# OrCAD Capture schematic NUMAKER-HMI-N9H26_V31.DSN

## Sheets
1 Audio: size A; title: NuMaker-HMI-N9H26; rev: 3.0; company: nuvoTon Technology Corp.; note: Audio
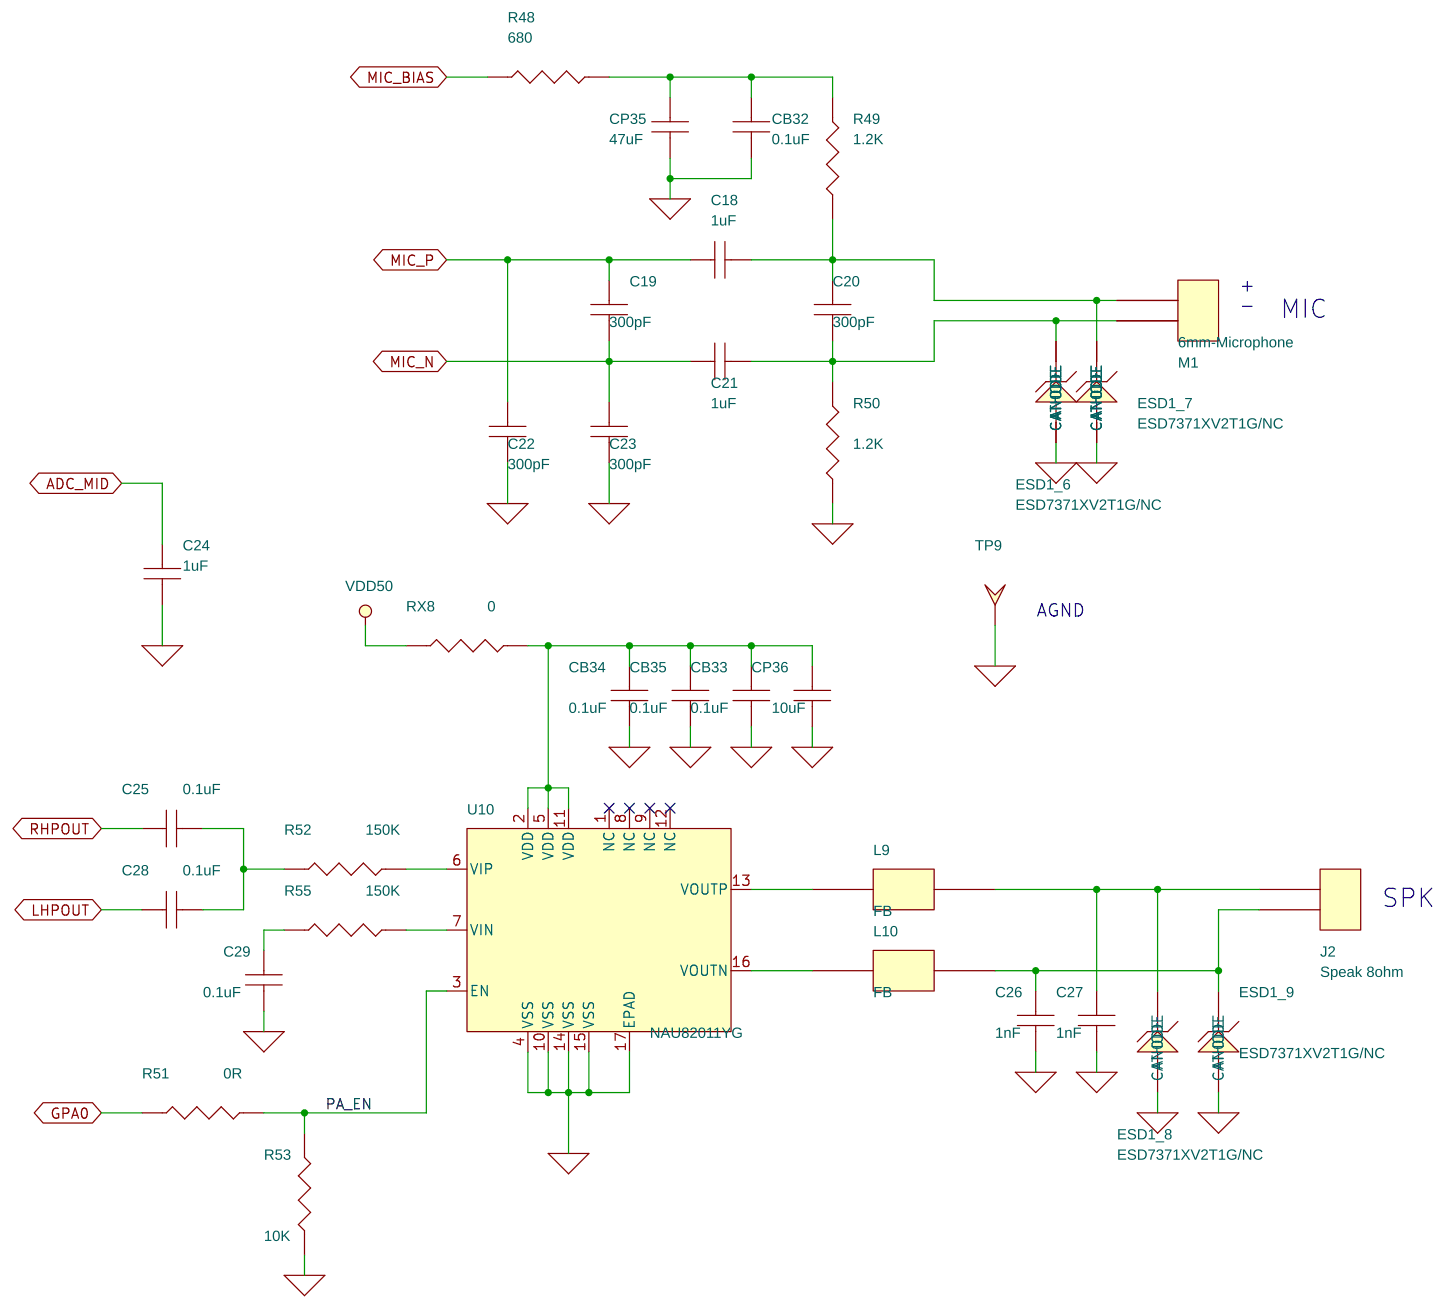
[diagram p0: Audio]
2 CPU: size B; note: CPU
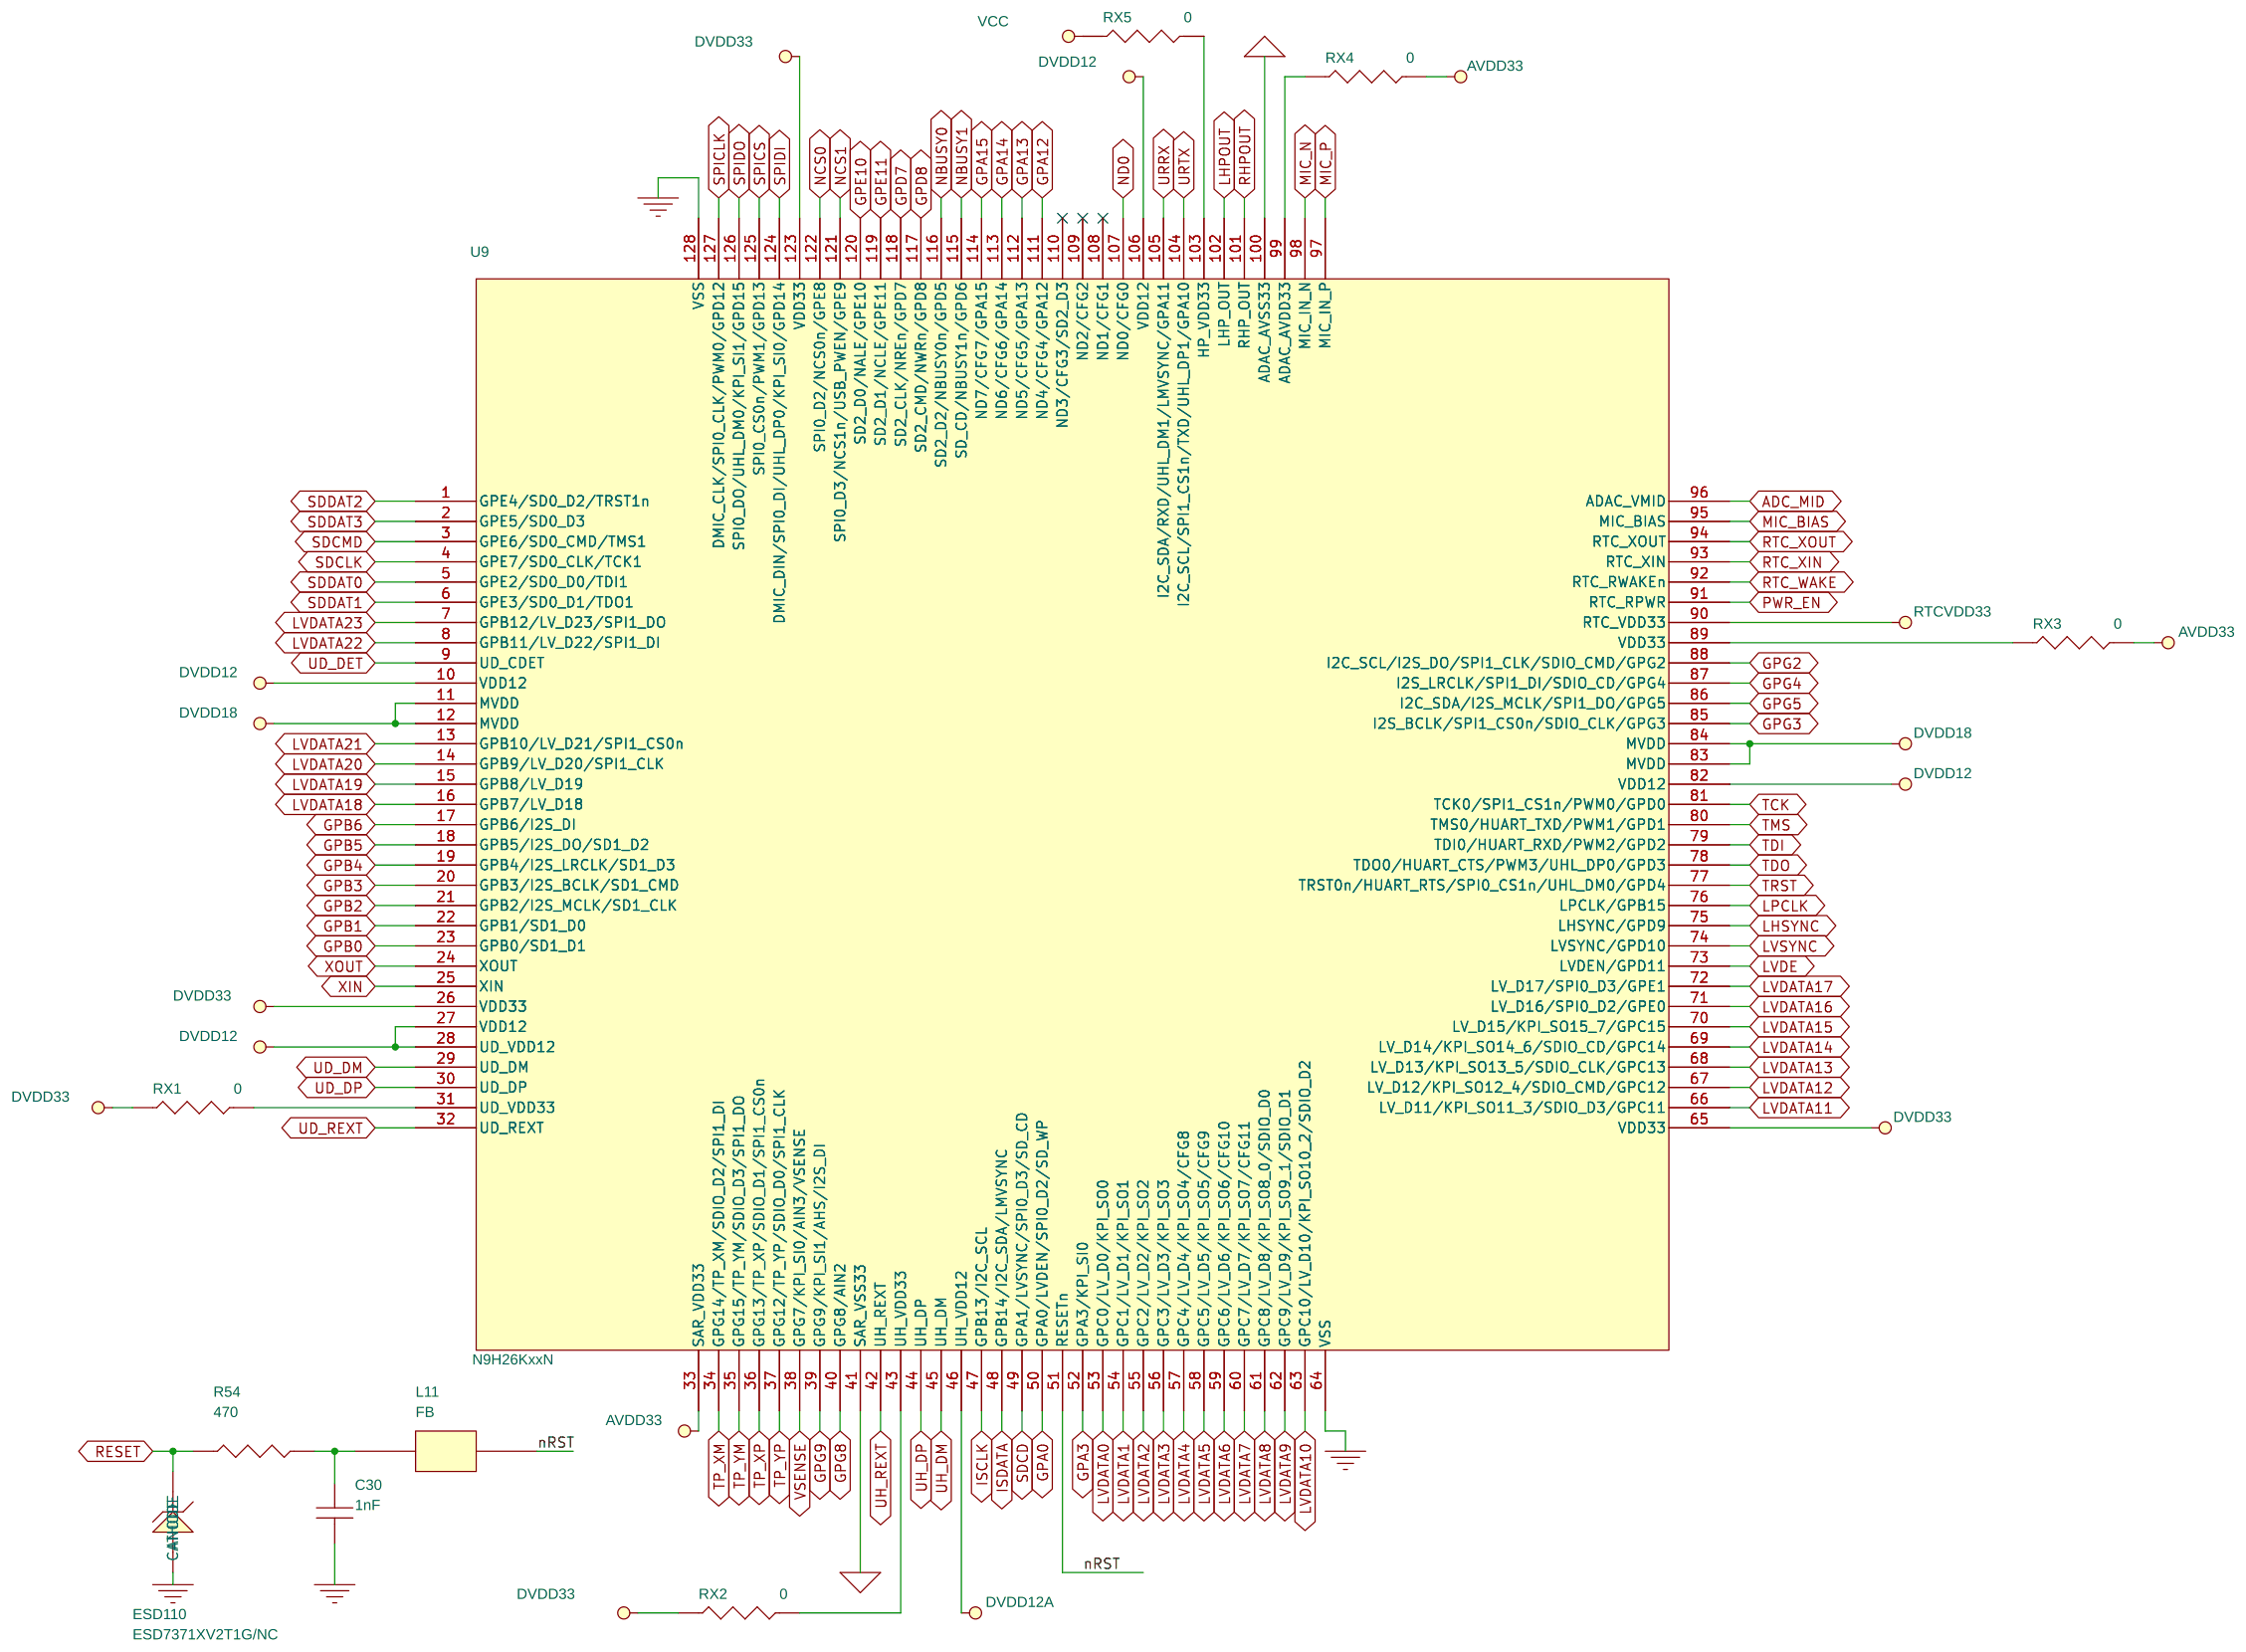
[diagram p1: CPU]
3 Debug: size A; note: Debug
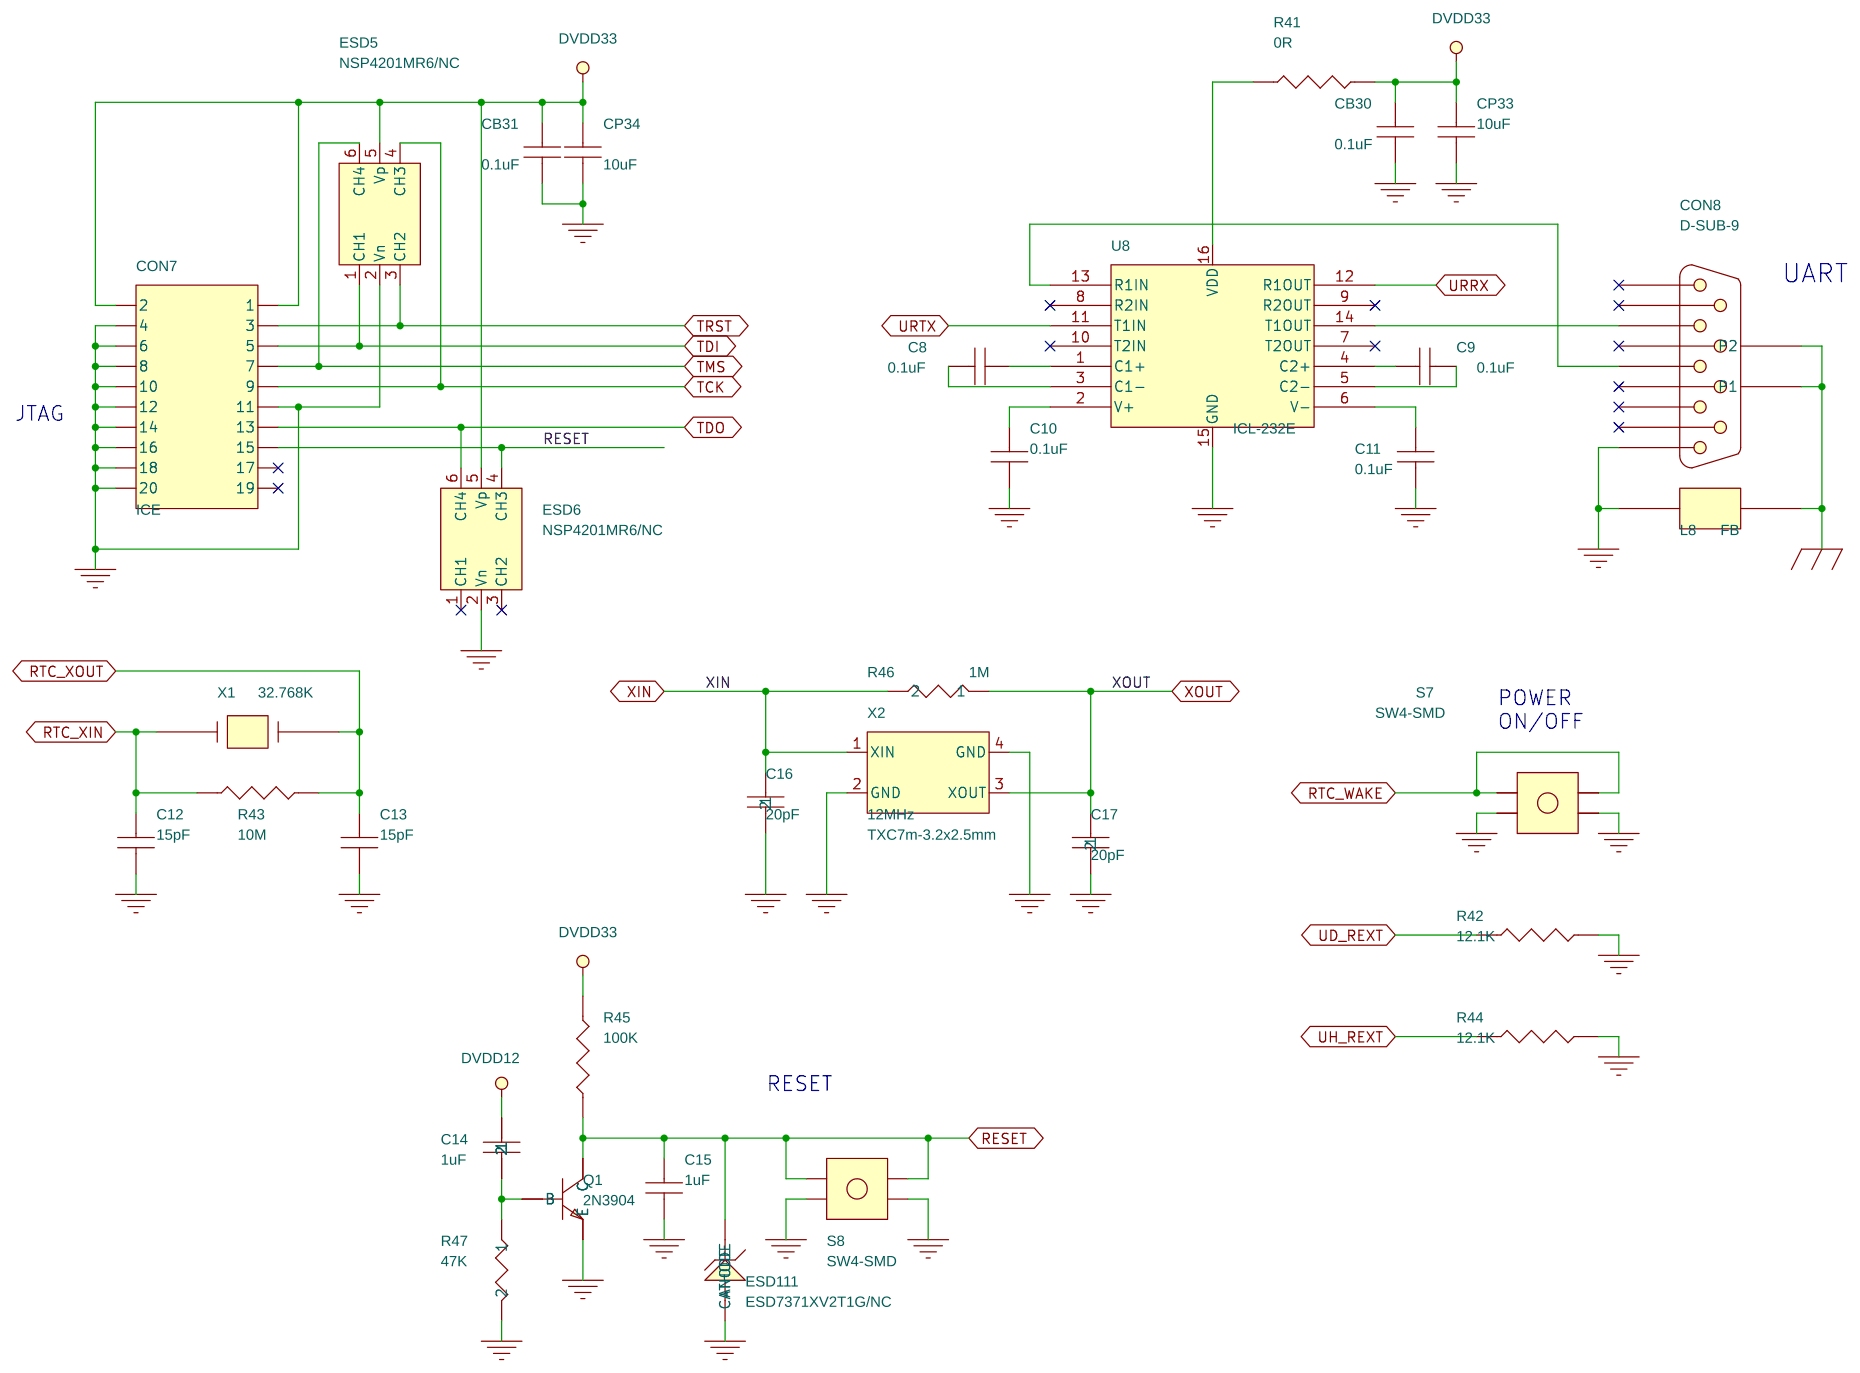
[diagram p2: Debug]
4 LCM: size B; note: LCM
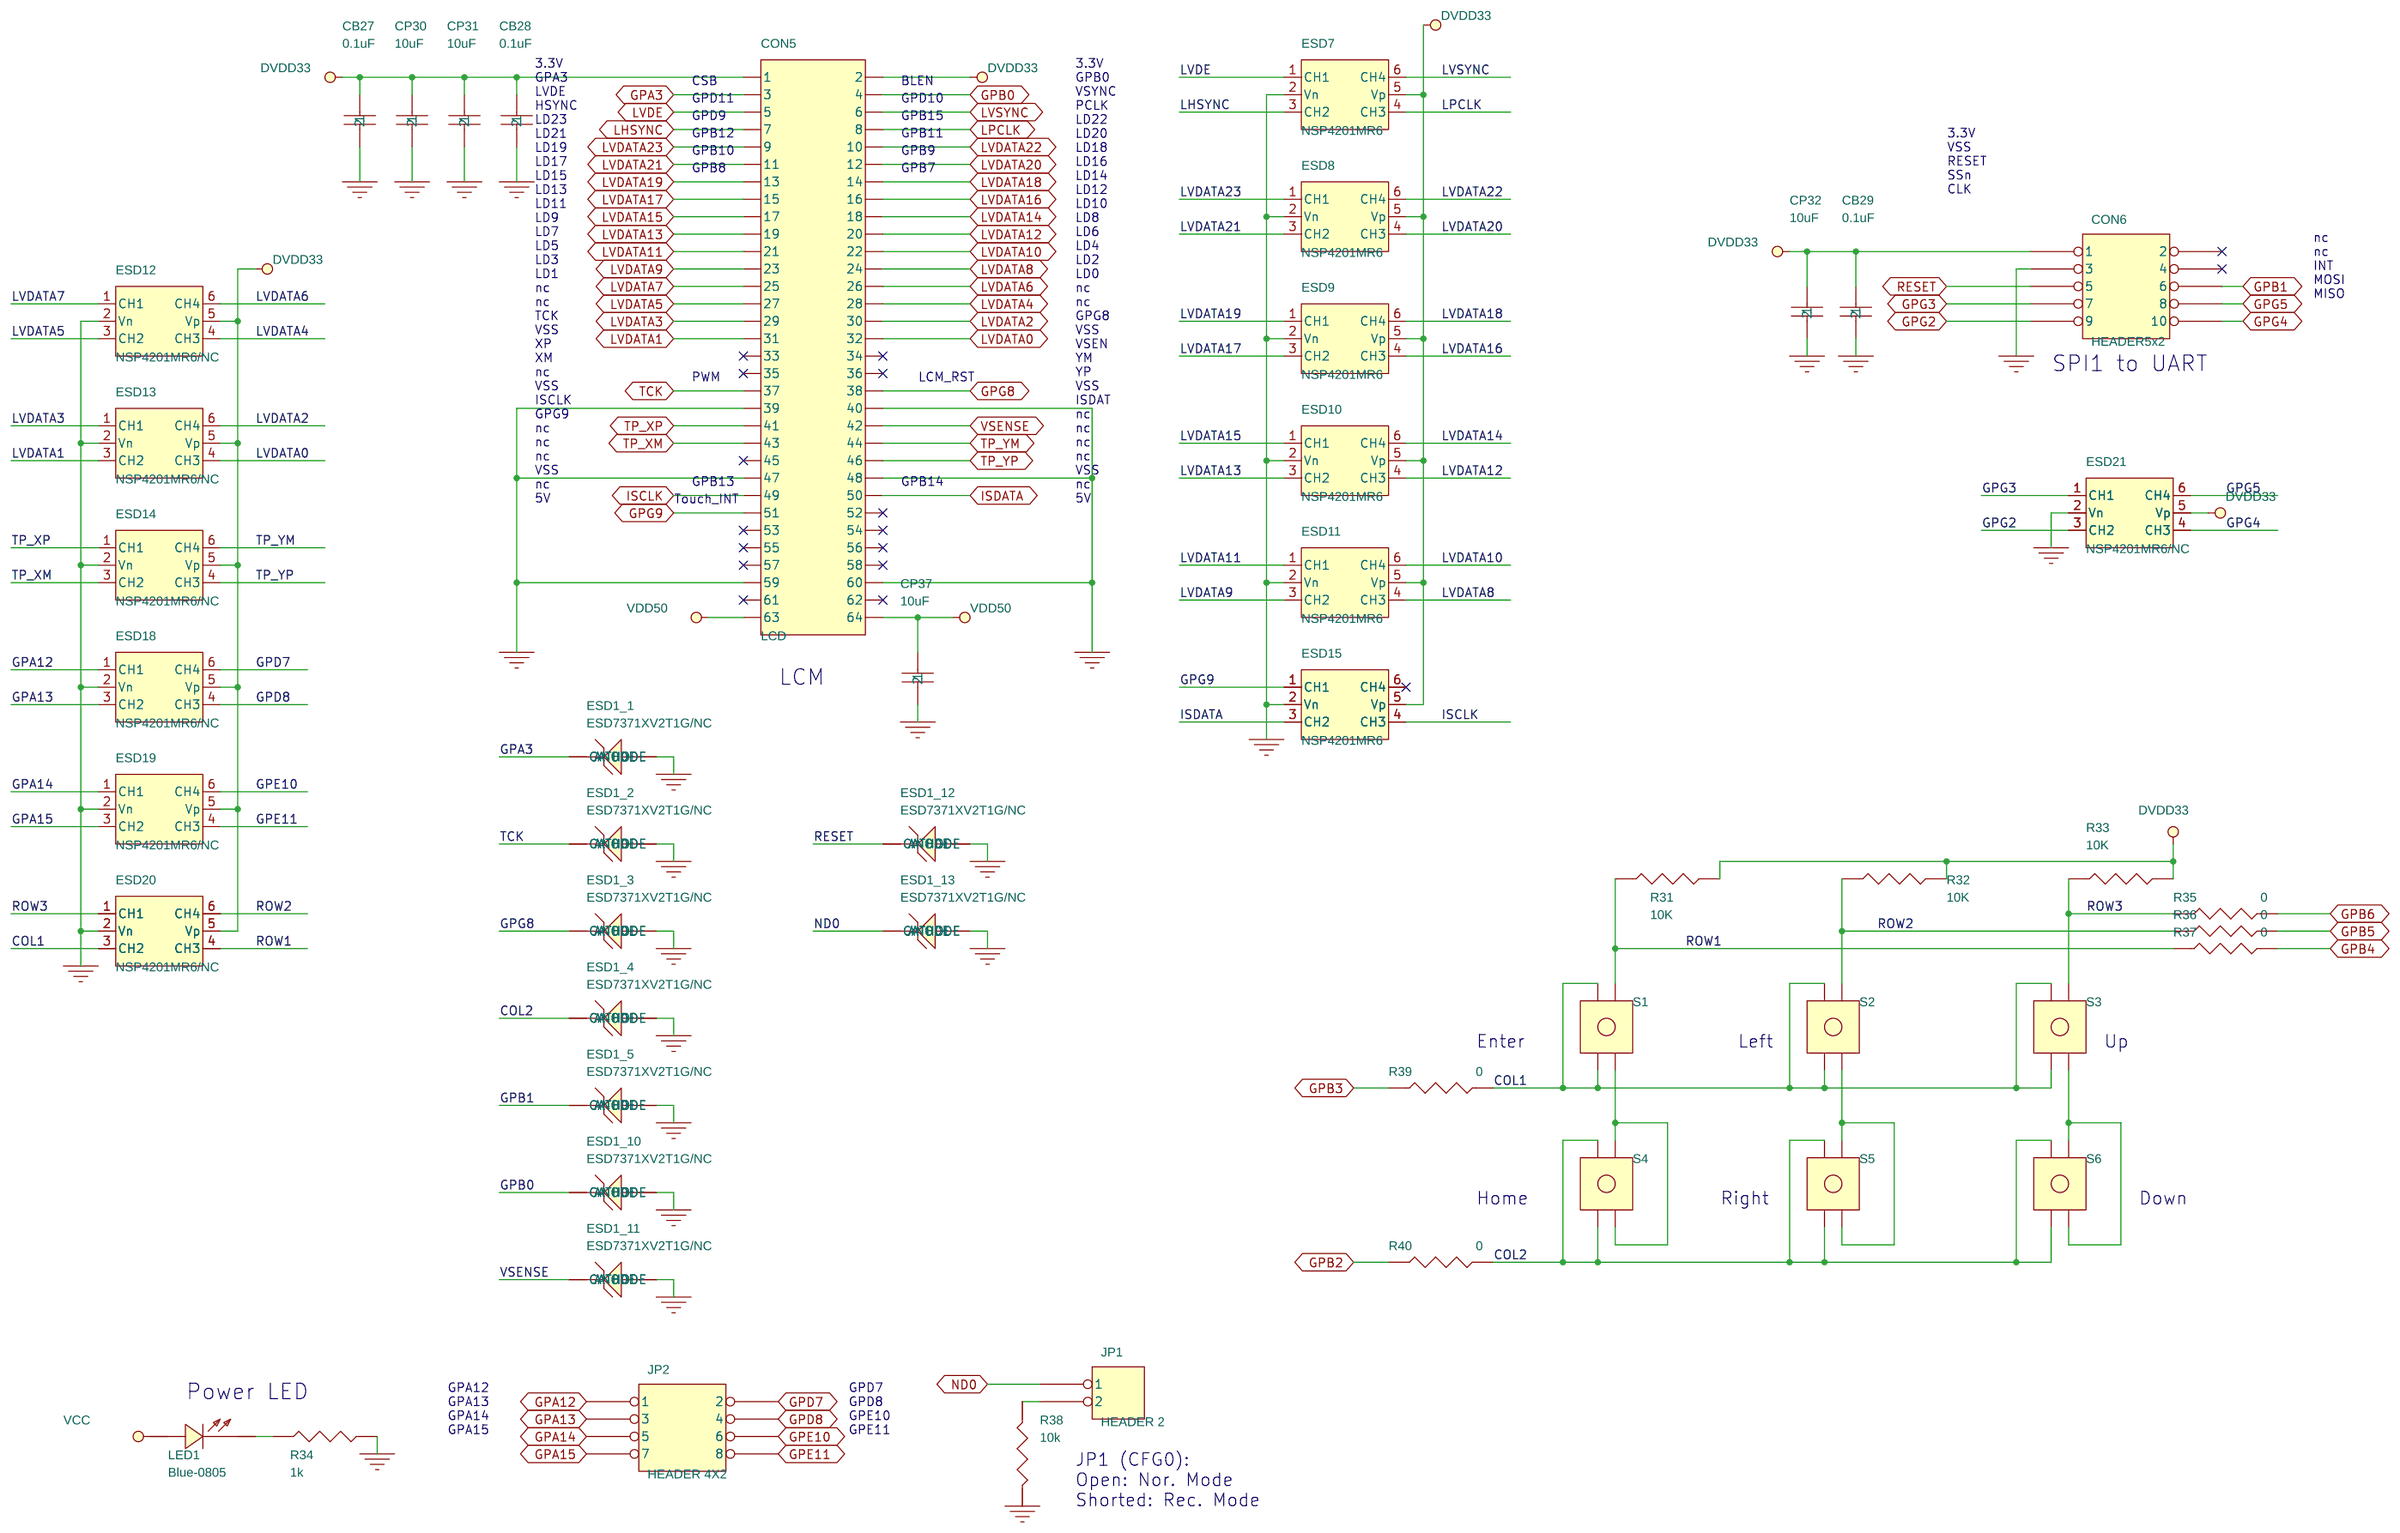
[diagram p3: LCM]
5 Memory: size A; note: Memory
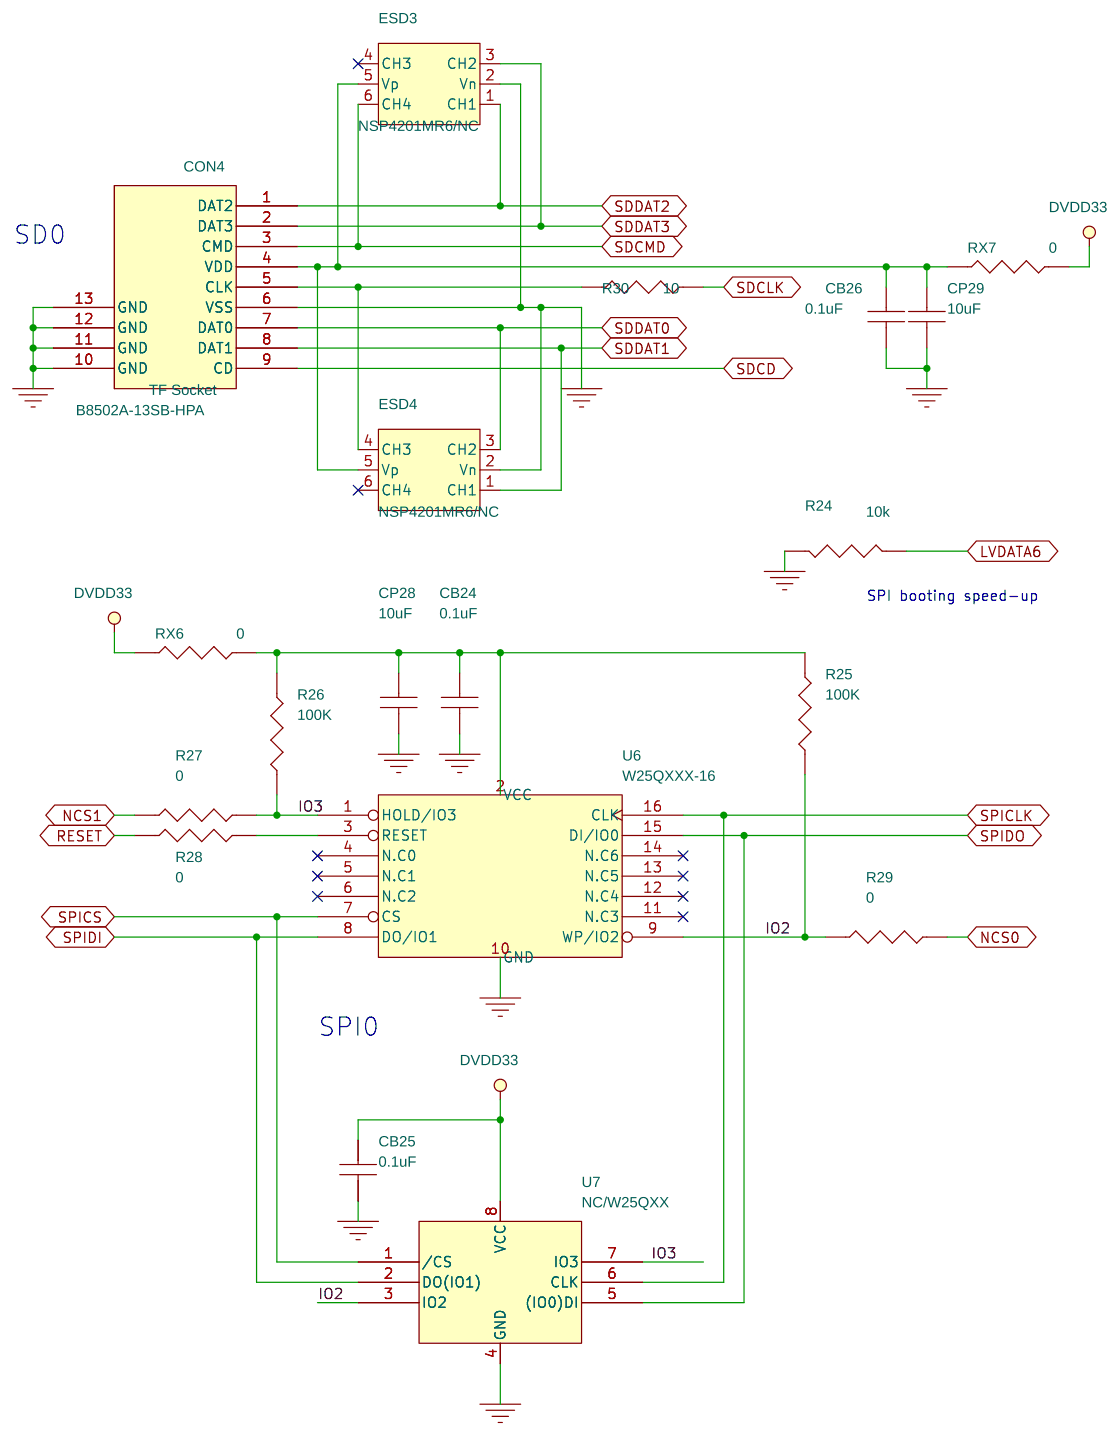
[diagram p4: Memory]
6 Power: size B; note: Power
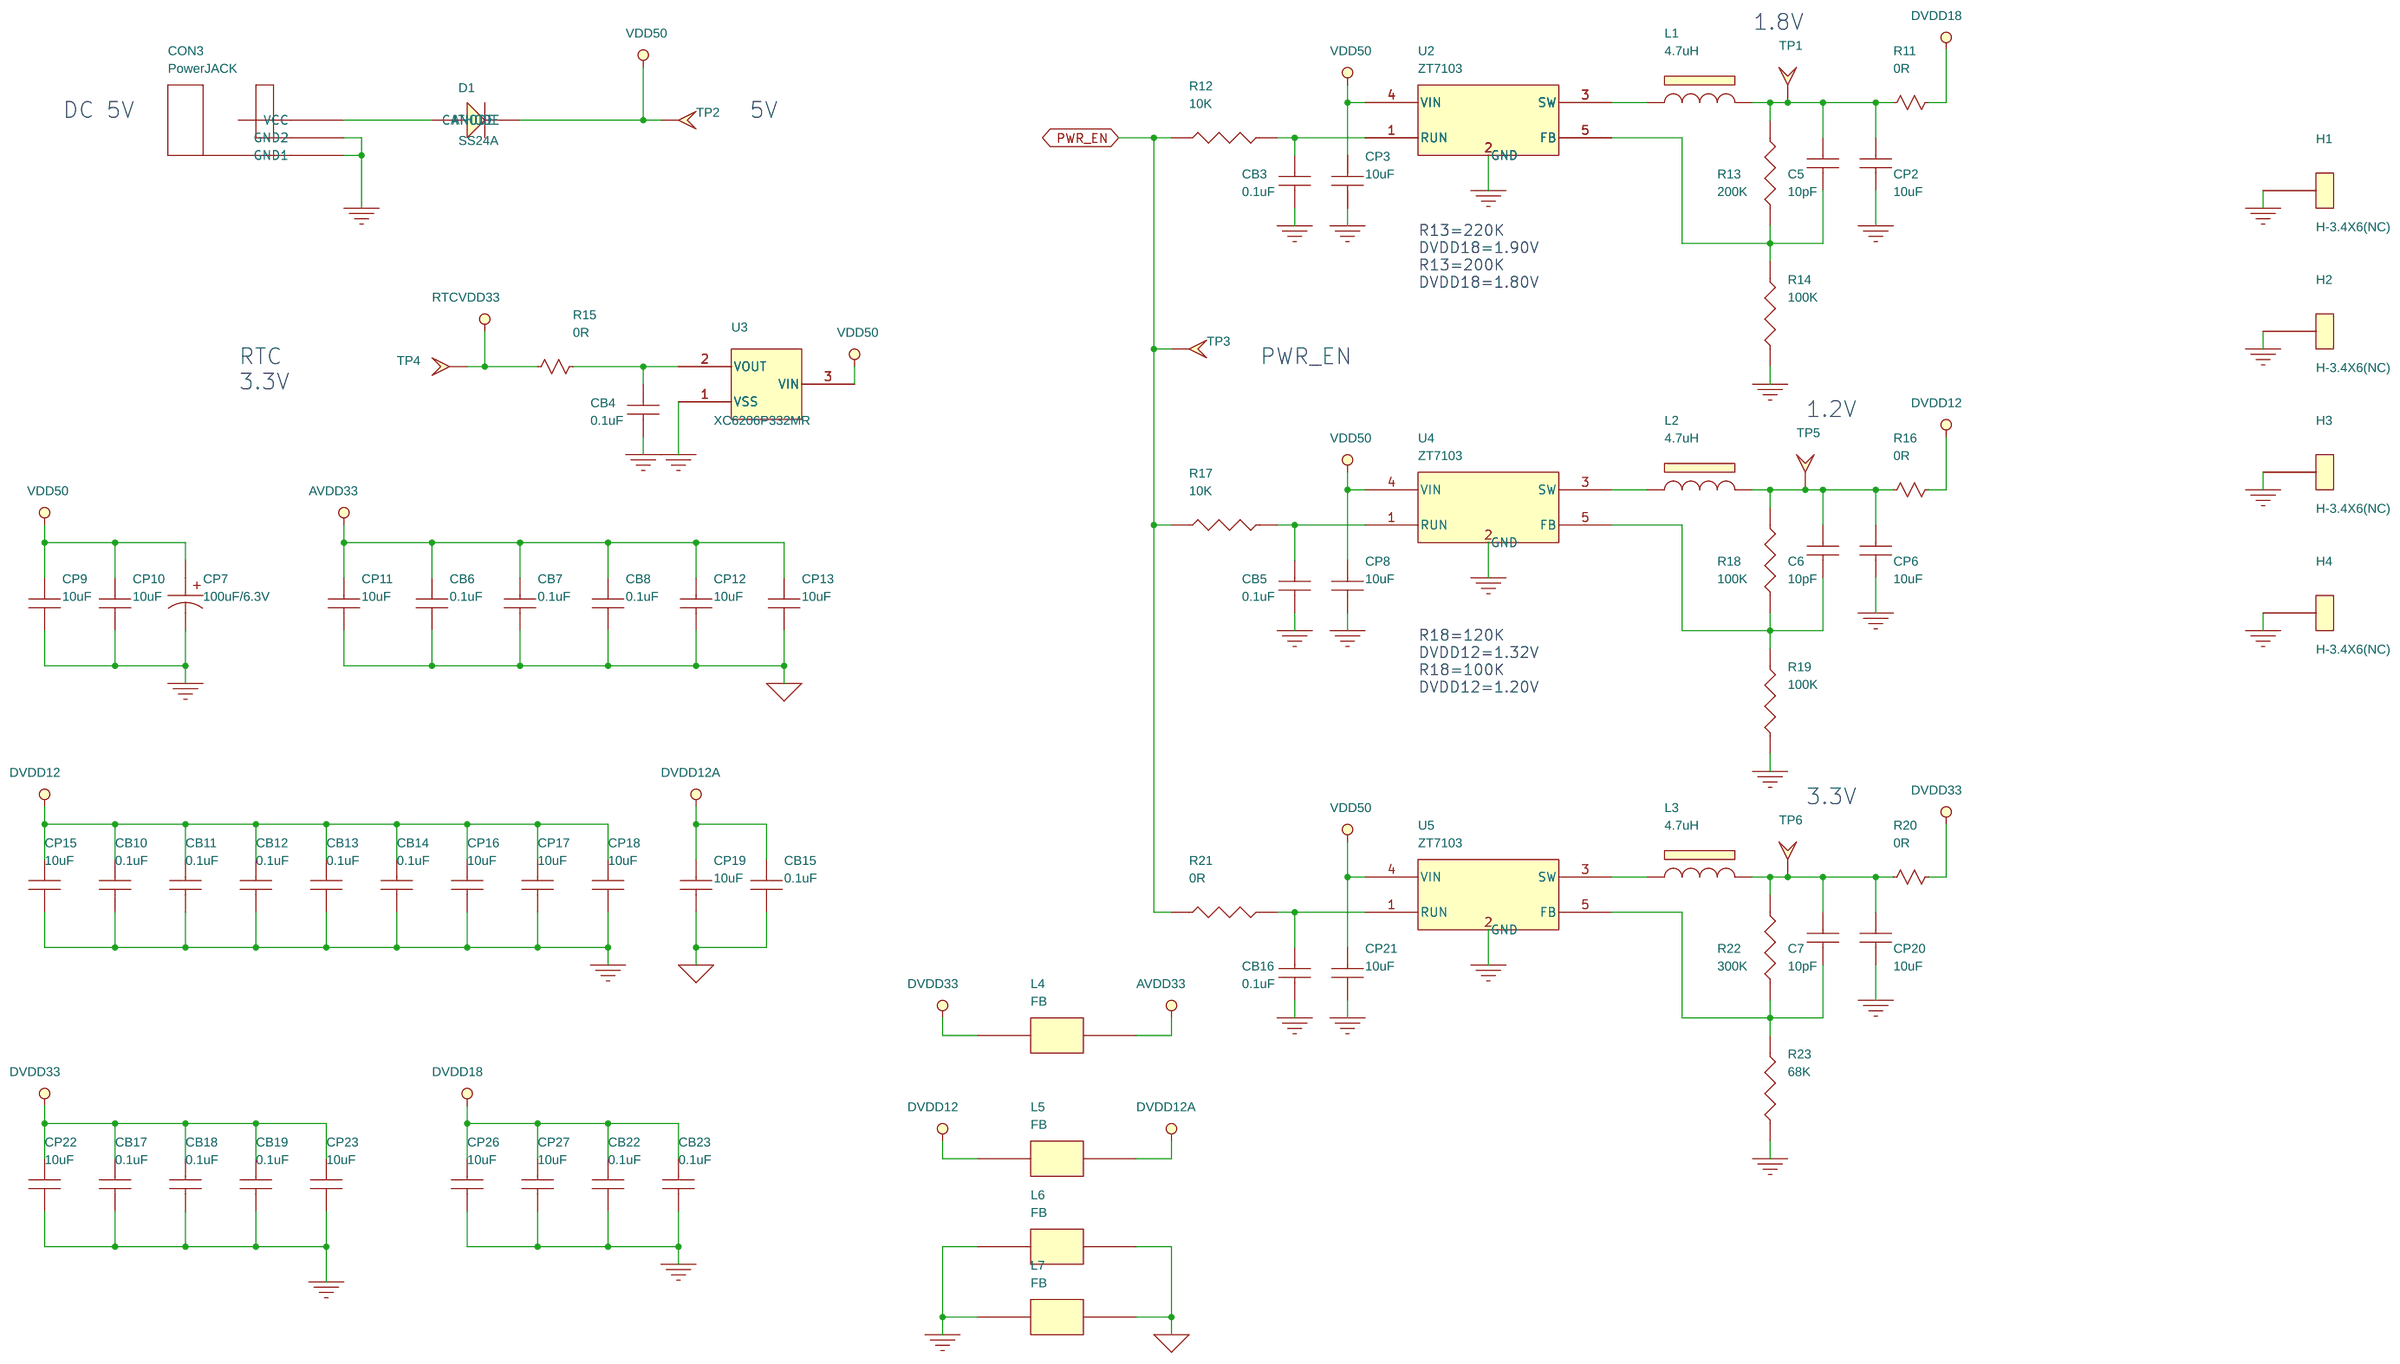
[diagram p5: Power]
7 USB: size A; note: USB
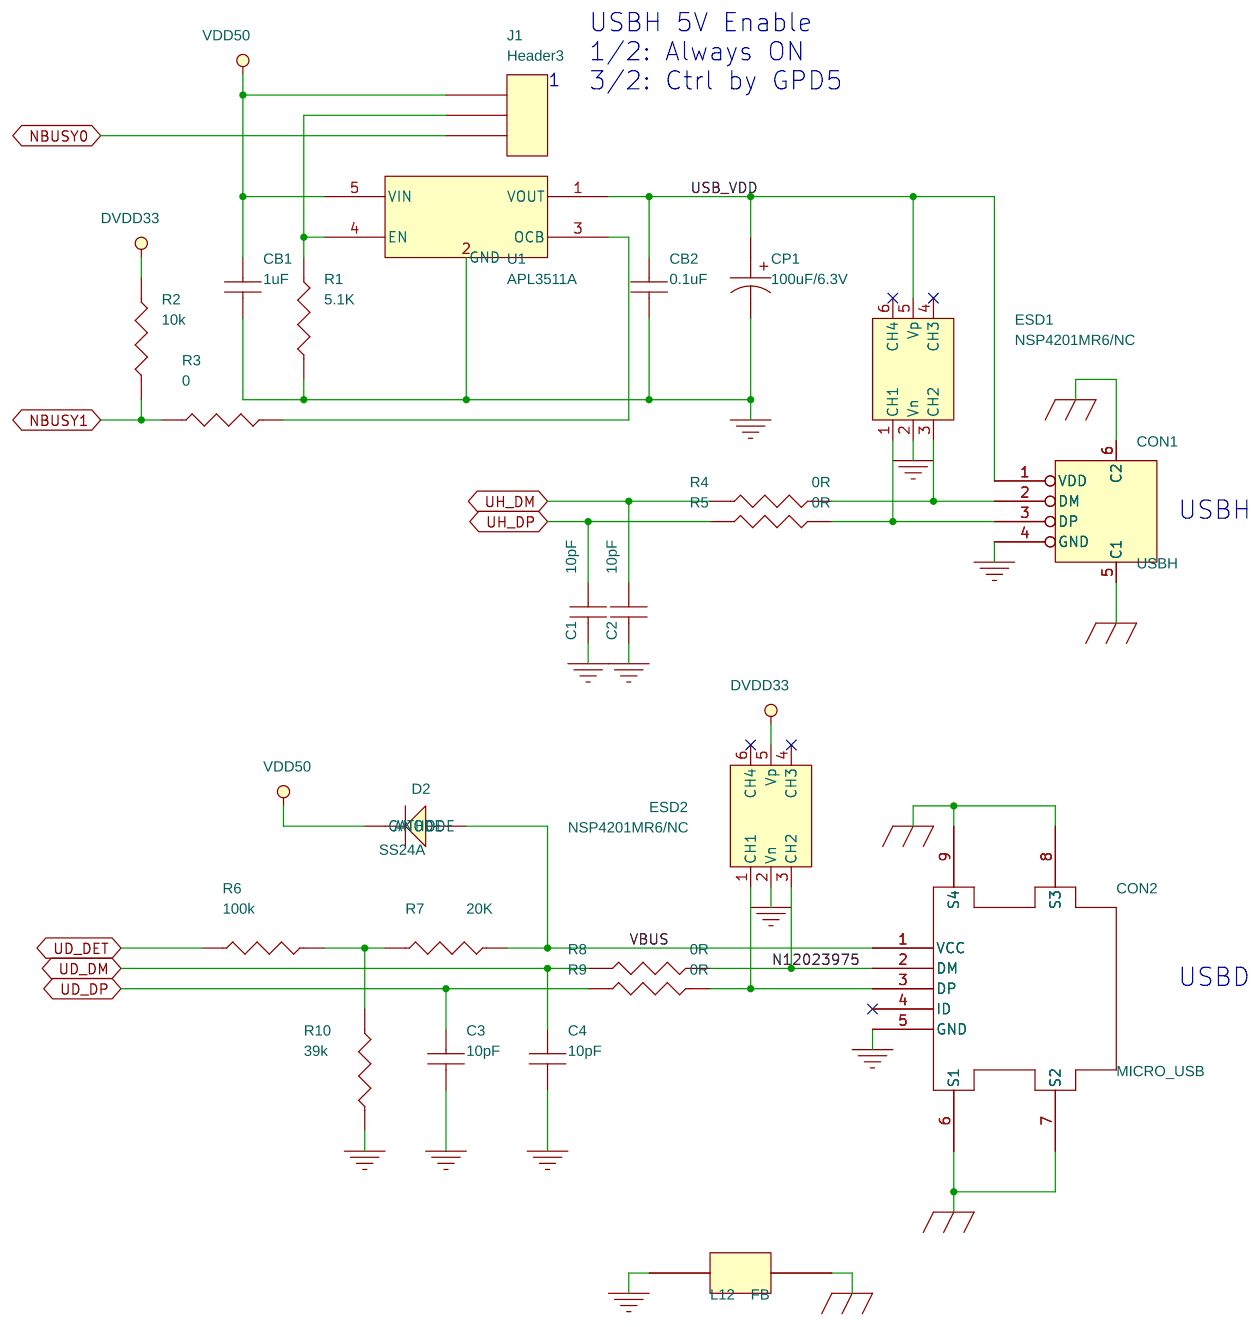
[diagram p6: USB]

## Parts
sheet Audio
C18  1uF  [0603C]
C19  300pF  [0603C]
C20  300pF  [0603C]
C21  1uF  [0603C]
C22  300pF  [0603C]
C23  300pF  [0603C]
C24  1uF  [0603C]
C25  0.1uF  [0603C]
C26  1nF  [0603C]
C27  1nF  [0603C]
C28  0.1uF  [0603C]
C29  0.1uF  [0603C]
CB32  0.1uF  [0603C]
CB33  0.1uF  [0603C]
CB34  0.1uF  [0603C]
CB35  0.1uF  [0603C]
CP35  47uF  [CAP_B]
CP36  10uF  [0603C]
ESD1_6  ESD7371XV2T1G/NC  [SOD-523/AC]
ESD1_7  ESD7371XV2T1G/NC  [SOD-523/AC]
ESD1_8  ESD7371XV2T1G/NC  [SOD-523/AC]
ESD1_9  ESD7371XV2T1G/NC  [SOD-523/AC]
J2  Speak 8ohm  [254MM-2PIN-1]
L9  FB  [0603L]
L10  FB  [0603L]
M1  6mm-Microphone  [MIC-6MM\LFM6027F]
R48  680  [0603R]
R49  1.2K  [0603R]
R50  1.2K  [0603R]
R51  0R  [0603R]
R52  150K  [0603R]
R53  10K  [0603R]
R55  150K  [0603R]
RX8  0  [0603R]
TP9  AGND/NC  [TPS]
U10  NAU82011YG  [QFN16]
sheet CPU
C30  1nF  [0603C]
ESD110  ESD7371XV2T1G/NC  [SOD-523/AC]
L11  FB  [0603L]
R54  470  [0603R]
RX1  0  [0603R]
RX2  0  [0603R]
RX3  0  [0603R]
RX4  0  [0603R]
RX5  0  [0603R]
U9  N9H26KxxN  [LQFP128]
sheet Debug
C8  0.1uF  [0603C]
C9  0.1uF  [0603C]
C10  0.1uF  [0603C]
C11  0.1uF  [0603C]
C12  15pF  [0603C]
C13  15pF  [0603C]
C14  1uF  [0603C]
C15  1uF  [0603C]
C16  20pF  [C0603]
C17  20pF  [C0603]
CB30  0.1uF  [0603C]
CB31  0.1uF  [0603C]
CON7  ICE  [HEADER10X2\BOX, 2.54mm 90 Degree]
CON8  D-SUB-9  [DB9_FMALE]
CP33  10uF  [0603C]
CP34  10uF  [0603C]
ESD5  NSP4201MR6/NC  [TSOP-6/0.95]
ESD6  NSP4201MR6/NC  [TSOP-6/0.95]
ESD111  ESD7371XV2T1G/NC  [SOD-523/AC]
L8  FB  [0603L]
Q1  2N3904  [SOT23-BEC]
R41  0R  [0603R]
R42  12.1K  [0603R]
R43  10M  [0603R]
R44  12.1K  [0603R]
R45  100K  [0603R]
R46  1M  [R0603]
R47  47K  [0603R]
S7  SW4-SMD  [SW4-SMD]
S8  SW4-SMD  [SW4-SMD]
U8  ICL-232E  [NSOIC-16L]
X1  32.768K  [9HT9]
X2  12MHz  [TXC7m-3.2x2.5mm]
sheet LCM
CB27  0.1uF  [0603C]
CB28  0.1uF  [0603C]
CB29  0.1uF  [0603C]
CON5  LCD  [M_DIN_32X2/2.54A]
CON6  HEADER5x2  [CON/5X2B/2.54/M]
CP30  10uF  [0603C]
CP31  10uF  [0603C]
CP32  10uF  [0603C]
CP37  10uF  [0603C]
ESD1_1  ESD7371XV2T1G/NC  [SOD-523/AC]
ESD1_2  ESD7371XV2T1G/NC  [SOD-523/AC]
ESD1_3  ESD7371XV2T1G/NC  [SOD-523/AC]
ESD1_4  ESD7371XV2T1G/NC  [SOD-523/AC]
ESD1_5  ESD7371XV2T1G/NC  [SOD-523/AC]
ESD1_10  ESD7371XV2T1G/NC  [SOD-523/AC]
ESD1_11  ESD7371XV2T1G/NC  [SOD-523/AC]
ESD1_12  ESD7371XV2T1G/NC  [SOD-523/AC]
ESD1_13  ESD7371XV2T1G/NC  [SOD-523/AC]
ESD7  NSP4201MR6  [TSOP-6/0.95]
ESD8  NSP4201MR6  [TSOP-6/0.95]
ESD9  NSP4201MR6  [TSOP-6/0.95]
ESD10  NSP4201MR6  [TSOP-6/0.95]
ESD11  NSP4201MR6  [TSOP-6/0.95]
ESD12  NSP4201MR6/NC  [TSOP-6/0.95]
ESD13  NSP4201MR6/NC  [TSOP-6/0.95]
ESD14  NSP4201MR6/NC  [TSOP-6/0.95]
ESD15  NSP4201MR6  [TSOP-6/0.95]
ESD18  NSP4201MR6/NC  [TSOP-6/0.95]
ESD19  NSP4201MR6/NC  [TSOP-6/0.95]
ESD20  NSP4201MR6/NC  [TSOP-6/0.95]
ESD21  NSP4201MR6/NC  [TSOP-6/0.95]
JP1  HEADER 2  [Header2_2.54mm]
JP2  HEADER 4X2  [HEADER4X2\2.54]
LED1  Blue-0805  [LED0805]
R31  10K  [0603R]
R32  10K  [0603R]
R33  10K  [0603R]
R34  1k  [0603R]
R35  0  [0603R]
R36  0  [0603R]
R37  0  [0603R]
R38  10k  [0603R]
R39  0  [0603R]
R40  0  [0603R]
S1  TS01M-BN-A-S1-PF  [SW4-SMD]
S2  TS01M-BN-A-S1-PF  [SW4-SMD]
S3  TS01M-BN-A-S1-PF  [SW4-SMD]
S4  TS01M-BN-A-S1-PF  [SW4-SMD]
S5  TS01M-BN-A-S1-PF  [SW4-SMD]
S6  TS01M-BN-A-S1-PF  [SW4-SMD]
sheet Memory
CB24  0.1uF  [0603C]
CB25  0.1uF  [0603C]
CB26  0.1uF  [0603C]
CON4  TF Socket  [B8502A-13SB-HPA]
CP28  10uF  [0603C]
CP29  10uF  [0603C]
ESD3  NSP4201MR6/NC  [TSOP-6/0.95]
ESD4  NSP4201MR6/NC  [TSOP-6/0.95]
R24  10k  [0603R]
R25  100K  [0603R]
R26  100K  [0603R]
R27  0  [0603R]
R28  0  [0603R]
R29  0  [0603R]
R30  10  [0603R]
RX6  0  [0603R]
RX7  0  [0603R]
U6  W25QXXX-16  [SOIC16_300]
U7  NC/W25QXX  [SOIC8_208]
sheet Power
C5  10pF  [0603C]
C6  10pF  [0603C]
C7  10pF  [0603C]
CB3  0.1uF  [0603C]
CB4  0.1uF  [0603C]
CB5  0.1uF  [0603C]
CB6  0.1uF  [0603C]
CB7  0.1uF  [0603C]
CB8  0.1uF  [0603C]
CB10  0.1uF  [0603C]
CB11  0.1uF  [0603C]
CB12  0.1uF  [0603C]
CB13  0.1uF  [0603C]
CB14  0.1uF  [0603C]
CB15  0.1uF  [0603C]
CB16  0.1uF  [0603C]
CB17  0.1uF  [0603C]
CB18  0.1uF  [0603C]
CB19  0.1uF  [0603C]
CB22  0.1uF  [0603C]
CB23  0.1uF  [0603C]
CON3  PowerJACK  [POWERJACK]
CP2  10uF  [0603C]
CP3  10uF  [0603C]
CP6  10uF  [0603C]
CP7  100uF/6.3V  [CAP_B]
CP8  10uF  [0603C]
CP9  10uF  [0603C]
CP10  10uF  [0603C]
CP11  10uF  [0603C]
CP12  10uF  [0603C]
CP13  10uF  [0603C]
CP15  10uF  [0603C]
CP16  10uF  [0603C]
CP17  10uF  [0603C]
CP18  10uF  [0603C]
CP19  10uF  [0603C]
CP20  10uF  [0603C]
CP21  10uF  [0603C]
CP22  10uF  [0603C]
CP23  10uF  [0603C]
CP26  10uF  [0603C]
CP27  10uF  [0603C]
D1  SS24A  [DO214AC]
H1  H-3.4X6(NC)  [H-250]
H2  H-3.4X6(NC)  [H-250]
H3  H-3.4X6(NC)  [H-250]
H4  H-3.4X6(NC)  [H-250]
L1  4.7uH  [1210L]
L2  4.7uH  [1210L]
L3  4.7uH  [1210L]
L4  FB  [0603L]
L5  FB  [0603L]
L6  FB  [0603L]
L7  FB  [0603L]
R11  0R  [0603R]
R12  10K  [0603R]
R13  200K  [0603R]
R14  100K  [0603R]
R15  0R  [0603R]
R16  0R  [0603R]
R17  10K  [0603R]
R18  100K  [0603R]
R19  100K  [0603R]
R20  0R  [0603R]
R21  0R  [0603R]
R22  300K  [0603R]
R23  68K  [0603R]
TP1  VDD18  [TPS]
TP2  VDD50  [TPS]
TP3  PWR_EN  [TPS]
TP4  RTCVDD33  [TPS]
TP5  DVDD12  [TPS]
TP6  DVDD33  [TPS]
U2  ZT7103  [SOT-23-5]
U3  XC6206P332MR  [SOT23]
U4  ZT7103  [SOT-23-5]
U5  ZT7103  [SOT-23-5]
sheet USB
C1  10pF  [0603C]
C2  10pF  [0603C]
C3  10pF  [0603C]
C4  10pF  [0603C]
CB1  1uF  [0603C]
CB2  0.1uF  [0603C]
CON1  USBH  [USB4P]
CON2  MICRO_USB  [MICRO_USB_AB_LS]
CP1  100uF/6.3V  [CAP_B]
D2  SS24A  [DO214AC]
ESD1  NSP4201MR6/NC  [TSOP-6/0.95]
ESD2  NSP4201MR6/NC  [TSOP-6/0.95]
J1  Header3  [200MM-3PIN-1]
L12  FB  [0603L]
R1  5.1K  [0603R]
R2  10k  [0603R]
R3  0  [0603R]
R4  0R  [0603R]
R5  0R  [0603R]
R6  100k  [0603R]
R7  20K  [0603R]
R8  0R  [0603R]
R9  0R  [0603R]
R10  39k  [0603R]
U1  APL3511A  [SOT-23-5]

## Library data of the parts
C1-C13 C15 C18-C30 CB1-CB8 CB10-CB19 CB22-CB26 CB30-CB35 CP2 CP3 CP6 CP8-CP13 CP15-CP23 CP26-CP29 CP33-CP36 = CAP-NP
ESD1_6 ESD1_13 = DIODE_ZENER1_3
ESD1_7 ESD1_12 ESD110 ESD111 = DIODE_ZENER1
ESD1_8 ESD1_10 = DIODE_ZENER1_1
ESD1_9 ESD1_11 = DIODE_ZENER1_2
J2 M1 = CON2
L4-L12 = FB
R1-R10 R12-R14 R17-R19 R21-R45 R48-R55 RX1-RX8 = RES
TP1-TP6 TP9 = TP
U10 = ISD8101_0
U9 = N9H26KxxN_0
C14 CP30 = CAP_NP_1
C16 CB28 = CAP_NP_2
C17 CP32 = CAP_NP
CON7 = CON20A
CON8 = DSUB9M_0
ESD1-ESD15 ESD18-ESD21 = PJ9293_0
Q1 = NPN_4
R46 = R
R47 = R_1
S1-S8 = TS01M-BN-A-S1-PF
U8 = ICL-232E_0
X1 = XTAL_4
X2 = Crystal_SMD_2
CB27 = CAP_NP_3
CB29 = CAP_NP_6
CON5 = CON40A_0
CON6 = HEADER_5X2
CP31 = CAP_NP_4
CP37 = CAP_NP_5
ESD1_1 = DIODE_ZENER1_5
ESD1_2 = DIODE_ZENER1_6
ESD1_3 = DIODE_ZENER1_7
ESD1_4 = DIODE_ZENER1_8
ESD1_5 = DIODE_ZENER1_4
JP1 = HEADER_2
JP2 = HEADER_4X2
LED1 = LED
CON4 = TF_Socket
U6 = W25QXXX-16
U7 = W25XXX_1
CON3 = PowerJACK
CP1 CP7 = CAP
D1 D2 = DIODE
H1-H4 = TEST_POINT
L1-L3 = Inductor_Ferrite
R11 R15 R16 R20 = 0_OHM,1_10W,1%,0603
U2 U4 U5 = APW7102
U3 = XC6206P182MR
CON1 = USBH_0
CON2 = MiniUSB_2
J1 = CONN_TRBLK_3
U1 = APL3511A_0

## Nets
AGND: C22.2(C1B) C23.2(C1B) C24.2(C1B) C26.2(C1B) C27.2(C1B) C29.2(C1B) CB6.2(C1B) CB7.2(C1B) CB8.2(C1B) CB15.2(C1B) CB32.2(C1B) CB33.2(C1B) CB34.2(C1B) CB35.2(C1B) CP11.2(C1B) CP12.2(C1B) CP13.2(C1B) CP19.2(C1B) CP35.2(C1B) CP36.2(C1B) ESD1_6.ANODE ESD1_7.ANODE ESD1_8.ANODE ESD1_9.ANODE L6.2 L7.2 R50.1(R1A) R53.1(R1A) TP9.1(TP) U9.41(SAR_VSS33) U9.100(ADAC_AVSS33) U10.4(VSS) U10.10(VSS) U10.14(VSS) U10.15(VSS) U10.17(EPAD)
AVDD33: CB6.1(C1A) CB7.1(C1A) CB8.1(C1A) CP11.1(C1A) CP12.1(C1A) CP13.1(C1A) L4.2 RX3.2(R1B) RX4.2(R1B) RX5.1(R1A) U9.33(SAR_VDD33)
DVDD12: C14.1 CB10.1(C1A) CB11.1(C1A) CB12.1(C1A) CB13.1(C1A) CB14.1(C1A) CP15.1(C1A) CP16.1(C1A) CP17.1(C1A) CP18.1(C1A) L5.1 R16.2 U9.10(VDD12) U9.27(VDD12) U9.28(UD_VDD12) U9.82(VDD12) U9.106(VDD12)
DVDD12A: CB15.1(C1A) CP19.1(C1A) L5.2 U9.46(UH_VDD12)
DVDD18: CB22.1(C1A) CB23.1(C1A) CP26.1(C1A) CP27.1(C1A) R11.2 U9.11(MVDD) U9.12(MVDD) U9.83(MVDD) U9.84(MVDD)
DVDD33: CB17.1(C1A) CB18.1(C1A) CB19.1(C1A) CB25.1(C1A) CB27.1 CB28.1 CB29.1 CB30.1(C1A) CB31.1(C1A) CON5.1 CON5.2 CON6.1 CON7.1 CON7.2 CP22.1(C1A) CP23.1(C1A) CP30.1 CP31.1 CP32.1 CP33.1(C1A) CP34.1(C1A) ESD2.5(Vp) ESD5.5(Vp) ESD6.5(Vp) ESD7.5(Vp) ESD8.5(Vp) ESD9.5(Vp) ESD10.5(Vp) ESD11.5(Vp) ESD12.5(Vp) ESD13.5(Vp) ESD14.5(Vp) ESD15.5(Vp) ESD18.5(Vp) ESD19.5(Vp) ESD20.5(Vp) ESD21.5(Vp) L4.1 LED1.1(ANODE) R2.2(R1B) R20.2 R31.1(R1A) R32.1(R1A) R33.1(R1A) R41.2(R1B) R45.1(R1A) RX1.1(R1A) RX2.1(R1A) RX6.1(R1A) RX7.2(R1B) U7.8(VCC) U9.26(VDD33) U9.65(VDD33) U9.123(VDD33)
GND: C1.2(C1B) C2.2(C1B) C3.2(C1B) C4.2(C1B) C10.2(C1B) C11.2(C1B) C12.2(C1B) C13.2(C1B) C15.2(C1B) C16.2 C17.2 C30.2(C1B) CB1.2(C1B) CB2.2(C1B) CB3.2(C1B) CB4.2(C1B) CB5.2(C1B) CB10.2(C1B) CB11.2(C1B) CB12.2(C1B) CB13.2(C1B) CB14.2(C1B) CB16.2(C1B) CB17.2(C1B) CB18.2(C1B) CB19.2(C1B) CB22.2(C1B) CB23.2(C1B) CB24.2(C1B) CB25.2(C1B) CB26.2(C1B) CB27.2 CB28.2 CB29.2 CB30.2(C1B) CB31.2(C1B) CON1.4(GND) CON2.5(GND) CON3.2(GND1) CON3.3(GND2) CON4.6(VSS) CON4.10(GND) CON4.11(GND) CON4.12(GND) CON4.13(GND) CON5.39 CON5.40 CON5.47 CON5.48 CON5.59 CON5.60 CON6.3 CON7.4 CON7.6 CON7.8 CON7.10 CON7.11 CON7.12 CON7.14 CON7.16 CON7.18 CON7.20 CON8.5 CP1.2(C1B) CP2.2(C1B) CP3.2(C1B) CP6.2(C1B) CP7.2(C1B) CP8.2(C1B) CP9.2(C1B) CP10.2(C1B) CP15.2(C1B) CP16.2(C1B) CP17.2(C1B) CP18.2(C1B) CP20.2(C1B) CP21.2(C1B) CP22.2(C1B) CP23.2(C1B) CP26.2(C1B) CP27.2(C1B) CP28.2(C1B) CP29.2(C1B) CP30.2 CP31.2 CP32.2 CP33.2(C1B) CP34.2(C1B) CP37.2 ESD1.2(Vn) ESD1_1.ANODE ESD1_2.ANODE ESD1_3.ANODE ESD1_4.ANODE ESD1_5.ANODE ESD1_10.ANODE ESD1_11.ANODE ESD1_12.ANODE ESD1_13.ANODE ESD2.2(Vn) ESD3.2(Vn) ESD4.2(Vn) ESD5.2(Vn) ESD6.2(Vn) ESD7.2(Vn) ESD8.2(Vn) ESD9.2(Vn) ESD10.2(Vn) ESD11.2(Vn) ESD12.2(Vn) ESD13.2(Vn) ESD14.2(Vn) ESD15.2(Vn) ESD18.2(Vn) ESD19.2(Vn) ESD20.2(Vn) ESD21.2(Vn) ESD110.ANODE ESD111.ANODE H1.1 H2.1 H3.1 H4.1 L6.1 L7.1 L8.1 L12.1 Q1.2(E) R1.1(R1A) R10.1(R1A) R14.1(R1A) R19.1(R1A) R23.1(R1A) R24.2(R1B) R34.1(R1A) R38.1(R1A) R42.1(R1A) R44.1(R1A) R47.2 S7.3 S7.4 S8.3 S8.4 U1.2(GND) U2.2(GND) U3.1(VSS) U4.2(GND) U5.2(GND) U6.10(GND) U7.4(GND) U8.15(GND) U9.64(VSS) U9.128(VSS) X2.2(GND) X2.4(GND)
GND_EARTH: CON8.10(P1) CON8.11(P2) L8.2
GND_USB: CON1.5(C1) CON1.6(C2) CON2.6(S1) CON2.7(S2) CON2.8(S3) CON2.9(S4) L12.2
VBUS: CON2.1(VCC) D2.ANODE R7.2(R1B)
VDD50: CB1.1(C1A) CON5.63 CON5.64 CP3.1(C1A) CP7.1(C1A) CP8.1(C1A) CP9.1(C1A) CP10.1(C1A) CP21.1(C1A) CP37.1 D1.CATHODE D2.CATHODE J1.1 RX8.1(R1A) TP2.1(TP) U1.5(VIN) U2.4(VIN) U3.3(VIN) U4.4(VIN) U5.4(VIN)
ADC_MID: C24.1(C1A) U9.96(ADAC_VMID)
COL1: ESD20.3(CH2) R39.1(R1A) S1.3 S1.4 S2.3 S2.4 S3.3 S3.4
COL2: ESD1_4.CATHODE R40.1(R1A) S4.3 S4.4 S5.3 S5.4 S6.3 S6.4
GPA0: R51.1(R1A) U9.50(GPA0/LVDEN/SPI0_D2/SD_WP)
GPA3: CON5.3 ESD1_1.CATHODE U9.52(GPA3/KPI_SI0)
GPA12: ESD18.1(CH1) JP2.1 U9.111(ND4/CFG4/GPA12)
GPA13: ESD18.3(CH2) JP2.3 U9.112(ND5/CFG5/GPA13)
GPA14: ESD19.1(CH1) JP2.5 U9.113(ND6/CFG6/GPA14)
GPA15: ESD19.3(CH2) JP2.7 U9.114(ND7/CFG7/GPA15)
GPB0: CON5.4 ESD1_10.CATHODE U9.23(GPB0/SD1_D1)
GPB1: CON6.6 ESD1_5.CATHODE U9.22(GPB1/SD1_D0)
GPB2: R40.2(R1B) U9.21(GPB2/I2S_MCLK/SD1_CLK)
GPB3: R39.2(R1B) U9.20(GPB3/I2S_BCLK/SD1_CMD)
GPB4: R37.1(R1A) U9.19(GPB4/I2S_LRCLK/SD1_D3)
GPB5: R36.1(R1A) U9.18(GPB5/I2S_DO/SD1_D2)
GPB6: R35.1(R1A) U9.17(GPB6/I2S_DI)
GPD7: ESD18.6(CH4) JP2.2 U9.118(SD2_CLK/NREn/GPD7)
GPD8: ESD18.4(CH3) JP2.4 U9.117(SD2_CMD/NWRn/GPD8)
GPE10: ESD19.6(CH4) JP2.6 U9.120(SD2_D0/NALE/GPE10)
GPE11: ESD19.4(CH3) JP2.8 U9.119(SD2_D1/NCLE/GPE11)
GPG2: CON6.9 ESD21.3(CH2) U9.88(I2C_SCL/I2S_DO/SPI1_CLK/SDIO_CMD/GPG2)
GPG3: CON6.7 ESD21.1(CH1) U9.85(I2S_BCLK/SPI1_CS0n/SDIO_CLK/GPG3)
GPG4: CON6.10 ESD21.4(CH3) U9.87(I2S_LRCLK/SPI1_DI/SDIO_CD/GPG4)
GPG5: CON6.8 ESD21.6(CH4) U9.86(I2C_SDA/I2S_MCLK/SPI1_DO/GPG5)
GPG8: CON5.38 ESD1_3.CATHODE U9.40(GPG8/AIN2)
GPG9: CON5.51 ESD15.1(CH1) U9.39(GPG9/KPI_SI1/AHS/I2S_DI)
IO2: R25.1(R1A) R29.2(R1B) U6.9(WP/IO2) U7.3(IO2)
IO3: R26.1(R1A) R27.1(R1A) U6.1(HOLD/IO3) U7.7(IO3)
ISCLK: CON5.49 ESD15.4(CH3) U9.47(GPB13/I2C_SCL)
ISDATA: CON5.50 ESD15.3(CH2) U9.48(GPB14/I2C_SDA/LMVSYNC)
LHPOUT: C28.1(C1A) U9.102(LHP_OUT)
LHSYNC: CON5.7 ESD7.3(CH2) U9.75(LHSYNC/GPD9)
LPCLK: CON5.8 ESD7.4(CH3) U9.76(LPCLK/GPB15)
LVDATA0: CON5.32 ESD13.4(CH3) U9.53(GPC0/LV_D0/KPI_SO0)
LVDATA1: CON5.31 ESD13.3(CH2) U9.54(GPC1/LV_D1/KPI_SO1)
LVDATA2: CON5.30 ESD13.6(CH4) U9.55(GPC2/LV_D2/KPI_SO2)
LVDATA3: CON5.29 ESD13.1(CH1) U9.56(GPC3/LV_D3/KPI_SO3)
LVDATA4: CON5.28 ESD12.4(CH3) U9.57(GPC4/LV_D4/KPI_SO4/CFG8)
LVDATA5: CON5.27 ESD12.3(CH2) U9.58(GPC5/LV_D5/KPI_SO5/CFG9)
LVDATA6: CON5.26 ESD12.6(CH4) R24.1(R1A) U9.59(GPC6/LV_D6/KPI_SO6/CFG10)
LVDATA7: CON5.25 ESD12.1(CH1) U9.60(GPC7/LV_D7/KPI_SO7/CFG11)
LVDATA8: CON5.24 ESD11.4(CH3) U9.61(GPC8/LV_D8/KPI_SO8_0/SDIO_D0)
LVDATA9: CON5.23 ESD11.3(CH2) U9.62(GPC9/LV_D9/KPI_SO9_1/SDIO_D1)
LVDATA10: CON5.22 ESD11.6(CH4) U9.63(GPC10/LV_D10/KPI_SO10_2/SDIO_D2)
LVDATA11: CON5.21 ESD11.1(CH1) U9.66(LV_D11/KPI_SO11_3/SDIO_D3/GPC11)
LVDATA12: CON5.20 ESD10.4(CH3) U9.67(LV_D12/KPI_SO12_4/SDIO_CMD/GPC12)
LVDATA13: CON5.19 ESD10.3(CH2) U9.68(LV_D13/KPI_SO13_5/SDIO_CLK/GPC13)
LVDATA14: CON5.18 ESD10.6(CH4) U9.69(LV_D14/KPI_SO14_6/SDIO_CD/GPC14)
LVDATA15: CON5.17 ESD10.1(CH1) U9.70(LV_D15/KPI_SO15_7/GPC15)
LVDATA16: CON5.16 ESD9.4(CH3) U9.71(LV_D16/SPI0_D2/GPE0)
LVDATA17: CON5.15 ESD9.3(CH2) U9.72(LV_D17/SPI0_D3/GPE1)
LVDATA18: CON5.14 ESD9.6(CH4) U9.16(GPB7/LV_D18)
LVDATA19: CON5.13 ESD9.1(CH1) U9.15(GPB8/LV_D19)
LVDATA20: CON5.12 ESD8.4(CH3) U9.14(GPB9/LV_D20/SPI1_CLK)
LVDATA21: CON5.11 ESD8.3(CH2) U9.13(GPB10/LV_D21/SPI1_CS0n)
LVDATA22: CON5.10 ESD8.6(CH4) U9.8(GPB11/LV_D22/SPI1_DI)
LVDATA23: CON5.9 ESD8.1(CH1) U9.7(GPB12/LV_D23/SPI1_DO)
LVDE: CON5.5 ESD7.1(CH1) U9.73(LVDEN/GPD11)
LVSYNC: CON5.6 ESD7.6(CH4) U9.74(LVSYNC/GPD10)
MIC_BIAS: R48.2(R1B) U9.95(MIC_BIAS)
MIC_N: C19.2(C1B) C21.1(C1A) C23.1(C1A) U9.98(MIC_IN_N)
MIC_P: C18.1(C1A) C19.1(C1A) C22.1(C1A) U9.97(MIC_IN_P)
NBUSY0: J1.3 U9.116(SD2_D2/NBUSY0n/GPD5)
NBUSY1: R2.1(R1A) R3.2(R1B) U9.115(SD_CD/NBUSY1n/GPD6)
NCS0: R29.1(R1A) U9.122(SPI0_D2/NCS0n/GPE8)
NCS1: R27.2(R1B) U9.121(SPI0_D3/NCS1n/USB_PWEN/GPE9)
ND0: ESD1_13.CATHODE JP1.1 U9.107(ND0/CFG0)
nRST: L11.2 U9.51(RESETn)
PA_EN: R51.2(R1B) R53.2(R1B) U10.3(EN)
PWR_EN: R12.2(R1B) R17.2(R1B) R21.2(R1B) TP3.1(TP) U9.91(RTC_RPWR)
RESET: C15.1(C1A) CON6.5 CON7.15 ESD1_12.CATHODE ESD6.4(CH3) ESD110.CATHODE ESD111.CATHODE Q1.3(C) R28.2(R1B) R45.2(R1B) R54.1(R1A) S8.1 S8.2
RHPOUT: C25.1(C1A) U9.101(RHP_OUT)
ROW1: ESD20.4(CH3) R31.2(R1B) R37.2(R1B) S1.1
ROW2: ESD20.6(CH4) R32.2(R1B) R36.2(R1B) S2.1
ROW3: ESD20.1(CH1) R33.2(R1B) R35.2(R1B) S3.1
RTC_WAKE: S7.1 S7.2 U9.92(RTC_RWAKEn)
RTC_XIN: C12.1(C1A) R43.1(R1A) U9.93(RTC_XIN) X1.1
RTC_XOUT: C13.1(C1A) R43.2(R1B) U9.94(RTC_XOUT) X1.2
RTCVDD33: R15.1 TP4.1(TP) U9.90(RTC_VDD33)
SDCD: CON4.9(CD) U9.49(GPA1/LVSYNC/SPI0_D3/SD_CD)
SDCLK: R30.2(R1B) U9.4(GPE7/SD0_CLK/TCK1)
SDCMD: CON4.3(CMD) ESD3.6(CH4) U9.3(GPE6/SD0_CMD/TMS1)
SDDAT0: CON4.7(DAT0) ESD4.3(CH2) U9.5(GPE2/SD0_D0/TDI1)
SDDAT1: CON4.8(DAT1) ESD4.1(CH1) U9.6(GPE3/SD0_D1/TDO1)
SDDAT2: CON4.1(DAT2) ESD3.1(CH1) U9.1(GPE4/SD0_D2/TRST1n)
SDDAT3: CON4.2(DAT3) ESD3.3(CH2) U9.2(GPE5/SD0_D3)
SPICLK: U6.16(CLK) U7.6(CLK) U9.127(DMIC_CLK/SPI0_CLK/PWM0/GPD12)
SPICS: U6.7(CS) U7.1(/CS) U9.125(SPI0_CS0n/PWM1/GPD13)
SPIDI: U6.8(DO/IO1) U7.2(DO(IO1)) U9.124(DMIC_DIN/SPI0_DI/UHL_DP0/KPI_SI0/GPD14)
SPIDO: U6.15(DI/IO0) U7.5((IO0)DI) U9.126(SPI0_DO/UHL_DM0/KPI_SI1/GPD15)
TCK: CON5.37 CON7.9 ESD1_2.CATHODE ESD5.4(CH3) U9.81(TCK0/SPI1_CS1n/PWM0/GPD0)
TDI: CON7.5 ESD5.1(CH1) U9.79(TDI0/HUART_RXD/PWM2/GPD2)
TDO: CON7.13 ESD6.6(CH4) U9.78(TDO0/HUART_CTS/PWM3/UHL_DP0/GPD3)
TMS: CON7.7 ESD5.6(CH4) U9.80(TMS0/HUART_TXD/PWM1/GPD1)
TP_XM: CON5.43 ESD14.3(CH2) U9.34(GPG14/TP_XM/SDIO_D2/SPI1_DI)
TP_XP: CON5.41 ESD14.1(CH1) U9.36(GPG13/TP_XP/SDIO_D1/SPI1_CS0n)
TP_YM: CON5.44 ESD14.6(CH4) U9.35(GPG15/TP_YM/SDIO_D3/SPI1_DO)
TP_YP: CON5.46 ESD14.4(CH3) U9.37(GPG12/TP_YP/SDIO_D0/SPI1_CLK)
TRST: CON7.3 ESD5.3(CH2) U9.77(TRST0n/HUART_RTS/SPI0_CS1n/UHL_DM0/GPD4)
UD_DET: R6.2(R1B) U9.9(UD_CDET)
UD_DM: C4.1(C1A) R8.1(R1A) U9.29(UD_DM)
UD_DP: C3.1(C1A) R9.1(R1A) U9.30(UD_DP)
UD_REXT: R42.2(R1B) U9.32(UD_REXT)
UH_DM: C2.1(C1A) R4.1(R1A) U9.45(UH_DM)
UH_DP: C1.1(C1A) R5.1(R1A) U9.44(UH_DP)
UH_REXT: R44.2(R1B) U9.42(UH_REXT)
URRX: U8.12(R1OUT) U9.105(I2C_SDA/RXD/UHL_DM1/LMVSYNC/GPA11)
URTX: U8.11(T1IN) U9.104(I2C_SCL/SPI1_CS1n/TXD/UHL_DP1/GPA10)
USB_VDD: CB2.1(C1A) CON1.1(VDD) CP1.1(C1A) ESD1.5(Vp) U1.1(VOUT)
VSENSE: CON5.42 ESD1_11.CATHODE U9.38(GPG7/KPI_SI0/AIN3/VSENSE)
XIN: C16.1 R46.2 U9.25(XIN) X2.1(XIN)
XOUT: C17.1 R46.1 U9.24(XOUT) X2.3(XOUT)
N06761: CON3.1(VCC) D1.ANODE
N07741: L1.1 U2.3(SW)
N07928: C5.1(C1A) CP2.1(C1A) L1.2 R11.1 R13.2(R1B) TP1.1(TP)
N07935: C5.2(C1B) R13.1(R1A) R14.2(R1B) U2.5(FB)
N09582: CB3.1(C1A) R12.1(R1A) U2.1(RUN)
N2481187: C14.2 Q1.1(B) R47.1
N11952164: R41.1(R1A) U8.16(VDD)
N11952188: CON8.2 U8.14(T1OUT)
N11952244: CON8.3 U8.13(R1IN)
N11952564: C8.1(C1A) U8.1(C1+)
N11952632: C8.2(C1B) U8.3(C1-)
N11952700: C10.1(C1A) U8.2(V+)
N11952974: C9.1(C1A) U8.4(C2+)
N11953090: C9.2(C1B) U8.5(C2-)
N11953138: C11.1(C1A) U8.6(V-)
N11955877: CB5.1(C1A) R17.1(R1A) U4.1(RUN)
N11997623: CB24.1(C1A) CP28.1(C1A) R25.2(R1B) R26.2(R1B) RX6.2(R1B) U6.2(VCC)
N12010230: CB26.1(C1A) CON4.4(VDD) CP29.1(C1A) ESD3.5(Vp) ESD4.5(Vp) RX7.1(R1A)
N12016746: J1.2 R1.2(R1B) U1.4(EN)
N12017459: R3.1(R1A) U1.3(OCB)
N12023975: CON2.2(DM) ESD2.3(CH2) R8.2(R1B)
N12023985: CON2.3(DP) ESD2.1(CH1) R9.2(R1B)
N12028792: R6.1(R1A) R7.1(R1A) R10.2(R1B)
N12073847: CB32.1(C1A) CP35.1(C1A) R48.1(R1A) R49.2(R1B)
N12073852: C18.2(C1B) C20.1(C1A) ESD1_7.CATHODE M1.1 R49.1(R1A)
N12073914: C20.2(C1B) C21.2(C1B) ESD1_6.CATHODE M1.2 R50.2(R1B)
N12252075: CON4.5(CLK) ESD4.4(CH3) R30.1(R1A)
N12552488: R28.1(R1A) U6.3(RESET)
N15573332: C6.1(C1A) CP6.1(C1A) L2.2 R16.1 R18.2(R1B) TP5.1(TP)
N15573444: L2.1 U4.3(SW)
N15573448: C6.2(C1B) R18.1(R1A) R19.2(R1B) U4.5(FB)
N15573897: C7.1(C1A) CP20.1(C1A) L3.2 R20.1 R22.2(R1B) TP6.1(TP)
N15574009: L3.1 U5.3(SW)
N15574013: C7.2(C1B) R22.1(R1A) R23.2(R1B) U5.5(FB)
N15574149: CB16.1(C1A) R21.1(R1A) U5.1(RUN)
N15583333: CB4.1(C1A) R15.2 U3.2(VOUT)
N16251482: RX4.1(R1A) U9.99(ADAC_AVDD33)
N16251784: RX3.1(R1A) U9.89(VDD33)
N16254724: RX2.2(R1B) U9.43(UH_VDD33)
N16883636: JP1.2 R38.2(R1B)
N16890763: S1.2 S4.1 S4.2
N16890831: S3.2 S6.1 S6.2
N16890855: S2.2 S5.1 S5.2
N16938281: CON1.3(DP) ESD1.1(CH1) R5.2(R1B)
N16938292: CON1.2(DM) ESD1.3(CH2) R4.2(R1B)
N16988195: C30.1(C1A) L11.1 R54.2(R1B)
N17010717: LED1.2(CATHODE) R34.2(R1B)
N17034252: RX5.2(R1B) U9.103(HP_VDD33)
N17035999: RX1.2(R1B) U9.31(UD_VDD33)
N17105468: CB33.1(C1A) CB34.1(C1A) CB35.1(C1A) CP36.1(C1A) RX8.2(R1B) U10.2(VDD) U10.5(VDD) U10.11(VDD)
N17105470: C26.1(C1A) ESD1_9.CATHODE J2.2 L10.2
N17105474: C27.1(C1A) ESD1_8.CATHODE J2.1 L9.2
N17105632: C25.2(C1B) C28.2(C1B) R52.1(R1A)
N17105642: R52.2(R1B) U10.6(VIP)
N17105681: R55.2(R1B) U10.7(VIN)
N17105683: C29.1(C1A) R55.1(R1A)
N17105753: L10.1 U10.16(VOUTN)
N17105755: L9.1 U10.13(VOUTP)

Not connected (* = marked no-connect by the designer): CON2 4(ID)*; CON5 33* 34* 35* 36* 45* 52* 53* 54* 55* 56* 57* 58* 61* 62*; CON6 2* 4*; CON7 17* 19*; CON8 1* 4* 6* 7* 8* 9*; ESD1 4(CH3)* 6(CH4)*; ESD2 4(CH3)* 6(CH4)*; ESD3 4(CH3)*; ESD4 6(CH4)*; ESD6 1(CH1)* 3(CH2)*; ESD15 6(CH4)*; U6 4(N.C0)* 5(N.C1)* 6(N.C2)* 11(N.C3)* 12(N.C4)* 13(N.C5)* 14(N.C6)*; U8 7(T2OUT)* 8(R2IN)* 9(R2OUT)* 10(T2IN)*; U9 108(ND1/CFG1)* 109(ND2/CFG2)* 110(ND3/CFG3/SD2_D3)*; U10 1(NC)* 8(NC)* 9(NC)* 12(NC)*

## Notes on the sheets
sheet 1
- +
  -
- MIC
- AGND
- SPK
sheet 3
- UART
- JTAG
- POWER
  ON/OFF
- RESET
sheet 4
- 3.3V
  GPA3
  LVDE
  HSYNC
  LD23
  LD21
  LD19
  LD17
  LD15
  LD13
  LD11
  LD9
  LD7
  LD5
  LD3
  LD1
  nc
  nc
  TCK
  VSS
  XP
  XM
  nc
  VSS
  ISCLK
  GPG9
  nc
  nc
  nc
  VSS
  nc
  5V
- CSB
- BLEN
- 3.3V
  GPB0
  VSYNC
  PCLK
  LD22
  LD20
  LD18
  LD16
  LD14
  LD12
  LD10
  LD8
  LD6
  LD4
  LD2
  LD0
  nc
  nc
  GPG8
  VSS
  VSEN
  YM
  YP
  VSS
  ISDAT
  nc
  nc
  nc
  nc
  VSS
  nc
  5V
- GPD11
- GPD10
- GPD9
- GPB15
- GPB12
- GPB11
- 3.3V
  VSS
  RESET
  SSn
  CLK
- GPB10
- GPB9
- GPB8
- GPB7
- nc
  nc
  INT
  MOSI
  MISO
- SPI1 to UART
- PWM
- LCM_RST
- GPB13
- GPB14
- Touch_INT
- LCM
- Enter
- Left
- Up
- Home
- Right
- Down
- Power LED
- GPA12
  GPA13
  GPA14
  GPA15
- GPD7
  GPD8
  GPE10
  GPE11
- JP1 (CFG0):
  Open: Nor. Mode
  Shorted: Rec. Mode
sheet 5
- SD0
- SPI booting speed-up
- SPI0
sheet 6
- 1.8V
- DC 5V
- 5V
- R13=220K
  DVDD18=1.90V
  R13=200K
  DVDD18=1.80V
- RTC
  3.3V
- PWR_EN
- 1.2V
- R18=120K
  DVDD12=1.32V
  R18=100K
  DVDD12=1.20V
- 3.3V
sheet 7
- USBH 5V Enable
  1/2: Always ON
  3/2: Ctrl by GPD5
- 1
- USBH
- USBD
